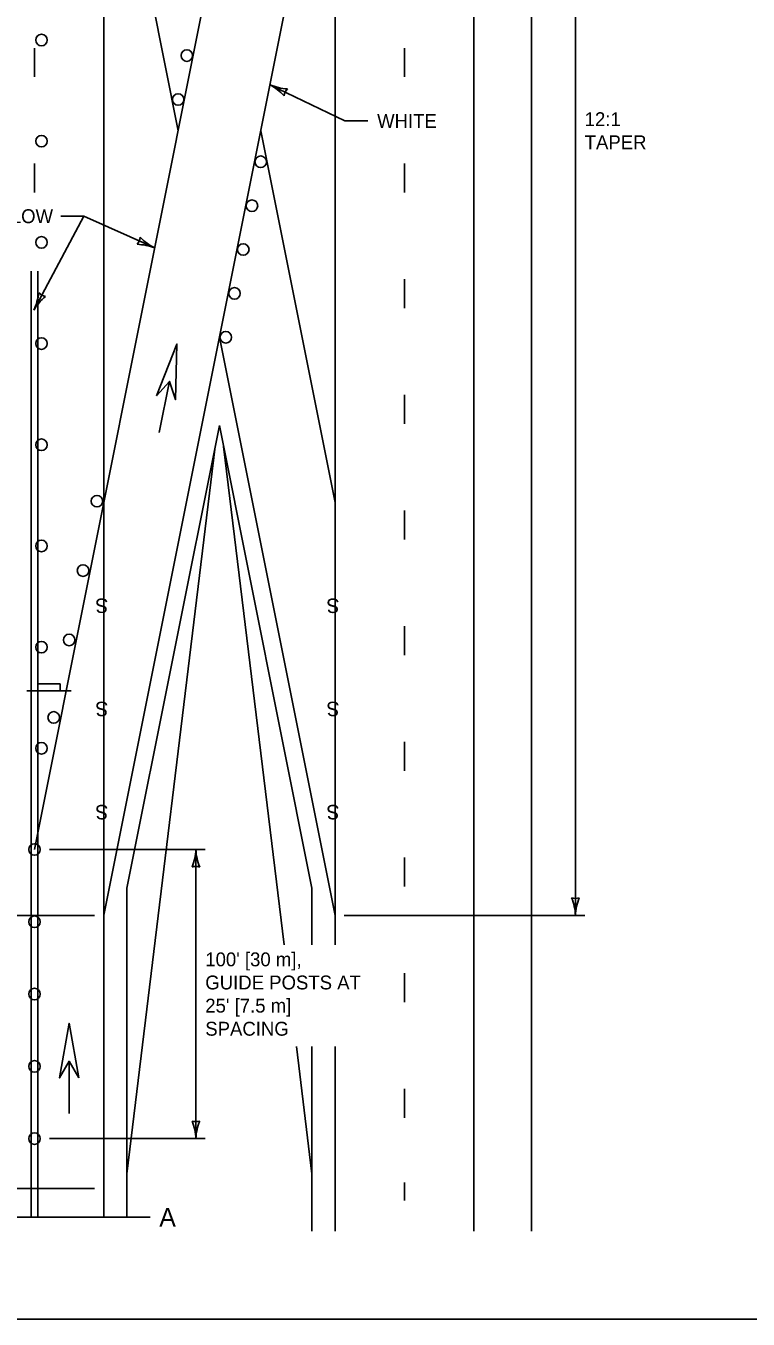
# Model space of a CAD drawing. Extents: x 49991.4 to 50021, y 49987.6 to 50011.4.
# Drawn here: x 50007.83 to 50010.95, y 49987.8 to 49993.39 of the extents above; entities that cross this region are included whole.
import ezdxf

# ---------------------------------------------------------------- set-up
doc = ezdxf.new("R2010")
doc.units = 0
for name, color, linetype in [('Level 1', 7, 'Continuous'), ('Level 2', 7, 'Continuous'), ('Level 3', 7, 'Continuous'), ('Level 6', 7, 'Continuous')]:
    doc.layers.add(name, color=color, linetype=linetype)

msp = doc.modelspace()

# ---------------------------------------------------------------- linework, layer by layer
at = {"layer": 'Level 1'}
for p, q in [((50009.765, 49988.1793), (50009.765, 49998.6725)), ((50010.015, 49988.1793), (50010.015, 49998.6725)), ((50007.865, 49989.8293), (50009.165, 49996.3295)), ((50008.165, 49989.5449), (50009.465, 49996.0449)), ((50008.165, 49991.3293), (50008.165, 49994.5446)), ((50008.4865, 49992.937), (50008.165, 49994.5446)), ((50009.165, 49991.3292), (50009.165, 49994.5449)), ((50007.865, 49993.1697), (50007.865, 49993.2947)), ((50009.465, 49993.1697), (50009.465, 49993.2947)), ((50009.165, 49991.3292), (50008.8434, 49992.9371)), ((50007.865, 49992.6697), (50007.865, 49992.7947)), ((50009.465, 49992.6697), (50009.465, 49992.7947)), ((50007.85, 49988.5793), (50007.85, 49992.3293)), ((50007.88, 49988.5793), (50007.88, 49992.3293)), ((50009.465, 49992.1697), (50009.465, 49992.2947)), ((50009.165, 49989.5447), (50008.665, 49992.0447)), ((50008.4038, 49991.6323), (50008.4485, 49991.8537)), ((50008.404, 49991.6323), (50008.4488, 49991.8537)), ((50009.465, 49991.6697), (50009.465, 49991.7947)), ((50008.265, 49989.6625), (50008.665, 49991.6625)), ((50009.065, 49989.6625), (50008.665, 49991.6625)), ((50008.265, 49988.4275), (50008.647, 49991.5723)), ((50008.9448, 49989.4173), (50008.683, 49991.5723)), ((50008.165, 49989.5447), (50008.165, 49991.3293)), ((50009.165, 49989.5447), (50009.165, 49991.3292)), ((50009.465, 49991.1697), (50009.465, 49991.2947)), ((50009.465, 49990.6697), (50009.465, 49990.7947)), ((50007.8316, 49990.5147), (50008.0236, 49990.5147)), ((50009.465, 49990.1697), (50009.465, 49990.2947)), ((50009.465, 49989.6697), (50009.465, 49989.7947)), ((50008.265, 49988.2392), (50008.265, 49989.6625)), ((50009.065, 49989.4173), (50009.065, 49989.6625)), ((50008.165, 49989.5449), (50008.165, 49988.3642)), ((50009.165, 49989.4173), (50009.165, 49989.5447)), ((50009.465, 49989.1697), (50009.465, 49989.2947)), ((50009.065, 49988.4275), (50008.9981, 49988.9773)), ((50009.065, 49988.1793), (50009.065, 49988.9773)), ((50009.165, 49988.1793), (50009.165, 49988.9773)), ((50008.0148, 49988.688), (50008.0148, 49988.9138)), ((50008.015, 49988.688), (50008.015, 49988.9138)), ((50009.465, 49988.6697), (50009.465, 49988.7947)), ((50007.85, 49988.2392), (50007.85, 49988.5793)), ((50007.88, 49988.2392), (50007.88, 49988.5793)), ((50008.165, 49988.2392), (50008.165, 49988.3642)), ((50009.465, 49988.3124), (50009.465, 49988.3892))]:
    msp.add_line(p, q, dxfattribs=at)
for points in [[(49999.3835, 49998.9992), (50016.7501, 49998.9992), (50016.7501, 49987.7988), (49999.3835, 49987.7988)], [(50008.3932, 49991.7913), (50008.4808, 49992.0149), (50008.4751, 49991.7747), (50008.4485, 49991.8535)], [(50007.9756, 49990.5451), (50007.8796, 49990.5451), (50007.8796, 49990.5147), (50007.9756, 49990.5147)], [(50008.0568, 49988.8416), (50008.015, 49989.078), (50007.9732, 49988.8416), (50008.015, 49988.9136)]]:
    msp.add_lwpolyline(points, close=True, dxfattribs=at)
for centre in [(50007.8953, 49993.3293), (50008.5242, 49993.262), (50008.4865, 49993.0723), (50007.8953, 49992.8918), (50008.8436, 49992.8029), (50008.8058, 49992.613), (50007.8953, 49992.4543), (50008.768, 49992.4234), (50008.7302, 49992.2337), (50007.8953, 49992.0168), (50008.6924, 49992.0441), (50007.8953, 49991.5793), (50008.1351, 49991.3353), (50007.8953, 49991.1418), (50008.0751, 49991.0353), (50008.0151, 49990.7353), (50007.8953, 49990.7043), (50007.9481, 49990.4003), (50007.8952, 49990.2668), (50007.865, 49989.8293), (50007.865, 49989.5169), (50007.865, 49989.2043), (50007.865, 49988.8918), (50007.865, 49988.5793)]:
    msp.add_circle(centre, 0.025, dxfattribs=at)
at = {"layer": 'Level 3'}
for p, q in [((50010.205, 49996.3295), (50010.205, 49989.5447)), ((50008.8832, 49993.1359), (50009.2071, 49992.9794)), ((50009.2071, 49992.9794), (50009.3071, 49992.9794)), ((50007.8622, 49992.1618), (50008.0791, 49992.5675)), ((50008.0791, 49992.5675), (50007.9791, 49992.5675)), ((50008.3852, 49992.4301), (50008.0791, 49992.5675)), ((50007.93, 49989.8293), (50008.6032, 49989.8293)), ((50008.5632, 49989.8293), (50008.5632, 49988.5793)), ((50006.752, 49989.5447), (50008.125, 49989.5447)), ((50010.245, 49989.5447), (50009.205, 49989.5447)), ((50007.93, 49988.5793), (50008.6032, 49988.5793)), ((50007.1653, 49988.3642), (50008.125, 49988.3642))]:
    msp.add_line(p, q, dxfattribs=at)
for centre, radius, start, end in [((50008.7783, 49992.9399), 0.2223, 41.6646, 61.8482), ((50008.9741, 49993.3505), 0.233, 247.0359, 266.2858), ((50008.9987, 49993.0802), 0.0548, 136.3475, 172.0698), ((50008.2682, 49992.4826), 0.0548, 317.9709, 353.6933), ((50008.3004, 49992.2131), 0.233, 68.6594, 87.9092), ((50008.4845, 49992.6291), 0.2223, 223.2881, 243.4716), ((50007.6515, 49992.2614), 0.233, 334.6977, 353.9475), ((50008.0538, 49992.049), 0.2223, 129.3264, 149.5099), ((50007.9226, 49992.2749), 0.0548, 224.0092, 259.7315), ((50008.3411, 49989.8385), 0.2223, 337.456, 357.6395), ((50008.7959, 49989.8408), 0.233, 182.8273, 202.0772), ((50008.5632, 49989.7011), 0.0548, 72.1388, 107.8612), ((50010.205, 49989.6729), 0.0548, 252.1388, 287.8612), ((50009.9723, 49989.5332), 0.233, 2.8273, 22.0772), ((50010.4271, 49989.5355), 0.2223, 157.456, 177.6395), ((50008.3411, 49988.5701), 0.2223, 2.3605, 22.544), ((50008.5632, 49988.7075), 0.0548, 252.1388, 287.8612), ((50008.7959, 49988.5678), 0.233, 157.9228, 177.1727)]:
    msp.add_arc(centre, radius, start, end, dxfattribs=at)
at = {"layer": 'Level 6'}
msp.add_line((50006.692, 49988.2392), (50008.365, 49988.2392), dxfattribs=at)

# ---------------------------------------------------------------- texts
at = {"layer": 'Level 1'}
for p in [(50008.1842, 49990.9146), (50009.1842, 49990.9145), (50008.1842, 49990.4684), (50009.1842, 49990.4684), (50008.1842, 49990.0222), (50009.1842, 49990.0222)]:
    msp.add_text('S', height=0.0625, rotation=180, dxfattribs=at).set_placement(p)
at = {"layer": 'Level 2'}
for s, height, p in [('WHITE', 0.06, (50009.3471, 49992.9494)), ('12:1', 0.06, (50010.245, 49992.9571)), ('TAPER', 0.06, (50010.245, 49992.8571)), ('YELLOW', 0.06, (50007.6109, 49992.5375)), ("100' [30 m], ", 0.06, (50008.6038, 49989.3243)), ('GUIDE POSTS AT ', 0.06, (50008.6038, 49989.2243)), ("25' [7.5 m] ", 0.06, (50008.6038, 49989.1243)), ('SPACING ', 0.06, (50008.6038, 49989.0243)), ('A', 0.08, (50008.405, 49988.1992))]:
    msp.add_text(s, height=height, dxfattribs=at).set_placement(p)

doc.saveas('drawing.dxf')
